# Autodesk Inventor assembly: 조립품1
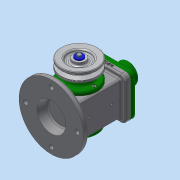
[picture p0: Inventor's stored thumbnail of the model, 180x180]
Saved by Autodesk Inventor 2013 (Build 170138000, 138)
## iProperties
Created: 2018-10
Part Number: 조립품1
Document SubType Name: Assembly
Designer: Administrator
Author: Administrator
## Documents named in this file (18)
- C:\Users\Administrator\Desktop\481007V1063\조립품1.iam
- C:\Users\Administrator\Desktop\481007V1063\부품1.ipt
- C:\Users\Administrator\Desktop\481007V1063\E-링.ipt
- C:\Users\Administrator\Desktop\481007V1063\V-벨트풀리.ipt
- C:\Users\Administrator\Desktop\481007V1063\덮개.ipt
- C:\Users\Administrator\Desktop\481007V1063\뒤커버.ipt
- C:\Users\Administrator\Desktop\481007V1063\링크.ipt
- C:\Users\Administrator\Desktop\481007V1063\베어링 17 x 40 x 12.ipt
- C:\Users\Administrator\Desktop\481007V1063\볼트 M4 x 8.ipt
- C:\Users\Administrator\Desktop\481007V1063\볼트 M4 x 10.ipt
- C:\Users\Administrator\Desktop\481007V1063\슬라이더.ipt
- C:\Users\Administrator\Desktop\481007V1063\앞커버.ipt
- C:\Users\Administrator\Desktop\481007V1063\오일 실 17 30 8.ipt
- C:\Users\Administrator\Desktop\481007V1063\와셔 4x16.ipt
- C:\Users\Administrator\Desktop\481007V1063\클레비스 핀 6 x 22.ipt
- 클레비스 핀 6 x 22.ipt
- C:\Users\Administrator\Desktop\481007V1063\키 4 x 4 x 12.ipt
- C:\Users\Administrator\Desktop\481007V1063\편심축.ipt
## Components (2 placed, 2 different names)
1. E-링:1
2. V-벨트풀리:1 — 플러쉬:1
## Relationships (1: Flush 1)
- 플러쉬:1 [Flush]: V-벨트풀리:1
